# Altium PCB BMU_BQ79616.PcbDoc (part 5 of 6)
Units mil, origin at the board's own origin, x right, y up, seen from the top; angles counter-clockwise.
Board outline 7605 x 4005 mil, 4 copper layers (Top Layer, Layer 1, Layer 2, Bottom Layer), stack 37.446 mil thick; 709 components, 447 nets, 2028 pads, 1862 vias.
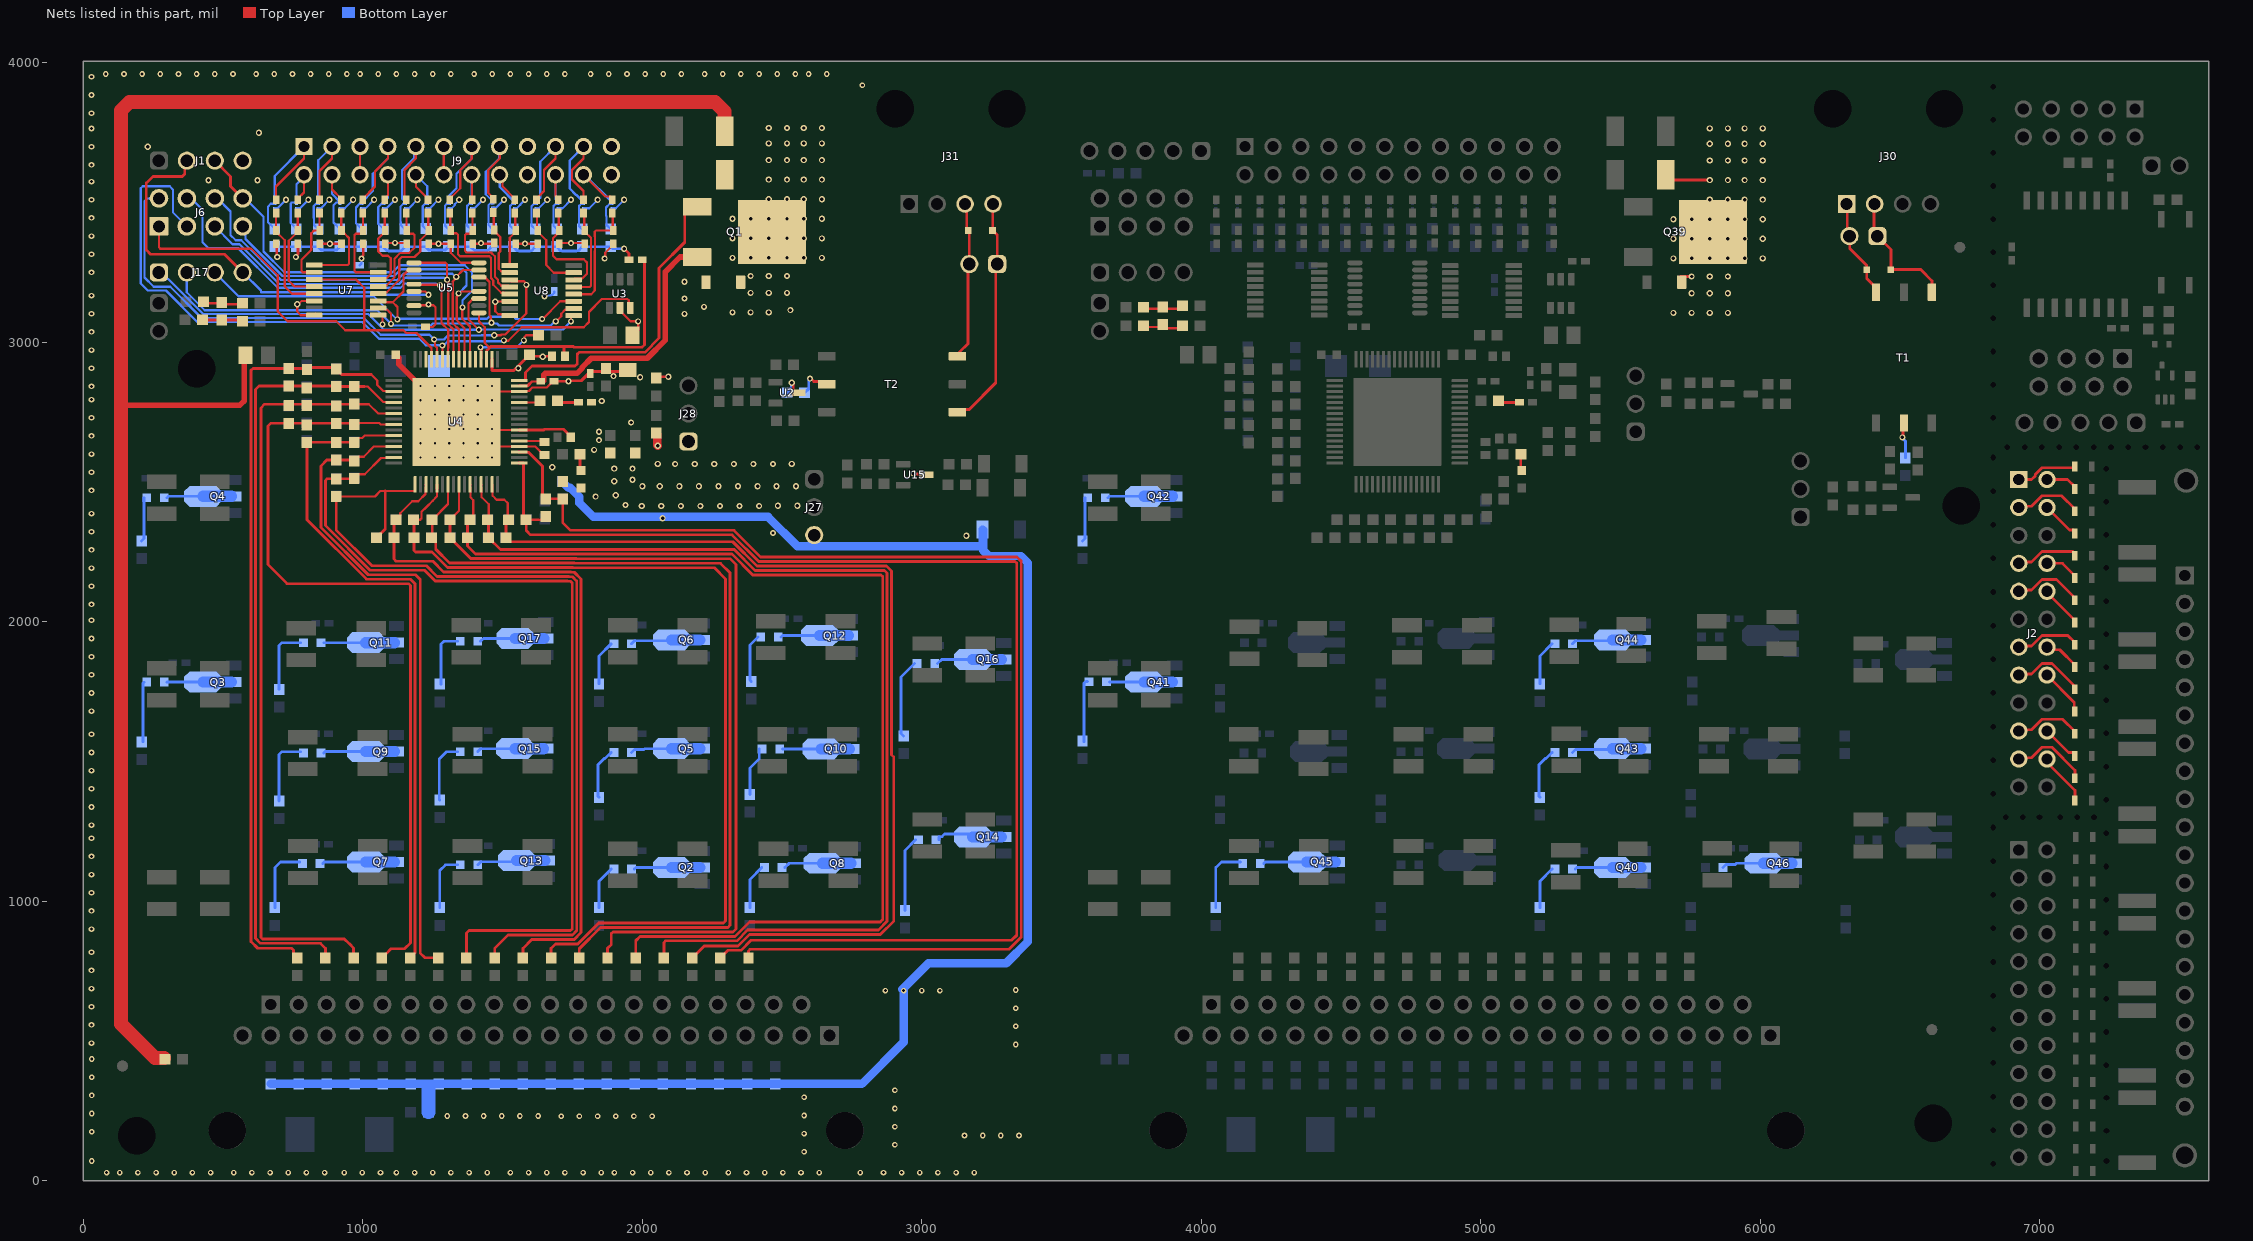
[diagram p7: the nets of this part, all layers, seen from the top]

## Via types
v1: diameter 20, hole 10, Top Layer to Bottom Layer, tented both sides, 1385 vias
v2: diameter 22.01, hole 12.01, Top Layer to Bottom Layer, tented both sides, 405 vias
v3: diameter 19.68, hole 7.87, Top Layer to Bottom Layer, 72 vias

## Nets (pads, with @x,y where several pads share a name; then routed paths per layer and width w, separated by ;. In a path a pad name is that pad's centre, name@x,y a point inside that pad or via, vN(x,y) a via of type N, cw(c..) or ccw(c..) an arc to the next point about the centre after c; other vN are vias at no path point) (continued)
A2_GND: C3.1 C8.2 C9.2 C10.1 C11.1 C12.1 C14.2 C16.1 C17.2 C18.1 C19.1 C20.2 C21.2 C22.2 C23.2 C24.2 C25.2 C26.2 C27.2 C28.2 C29.2 C31.2 C32.2 C33.2 C34.2 C35.2 C36.2 C37.2 C38.2 C39.1 C42.2 C43.2 C47.2 C50.2 C51.2 C79.2 C82.2 C83.2 C84.2 C85.2 C86.2 C88.2 C89.2 C90.2 C91.2 C92.2 C93.2 C94.2 C95.2 C96.2 C97.2 C98.2 C99.2 C100.2 C101.2 C102.2 C152.2 C153.1 D1.1 D2.2 D6.2 D7.2 D36.2 D37.2 D38.2 D39.2 D40.2 D43.2 D46.2 D49.2 D50.2 D51.2 D52.2 D53.2 D54.2 D55.2 J1.4 J9.5 J9.6 J9.11 J9.12 J9.17 J9.18 J9.23 J9.24 J27.3 J28.1 R9.1 U2.3 U3.2 U4.36 U4.39 U4.46 U4.50 U4.65 U5.8 U5.15 U7.6 U7.8 U8.6 U8.8 U15.3 | length 11070.7
  Top Layer w8: U7.6@826,3148.23 781.01,3148.23 768.79,3136 v2(765,3136) 765,3110 777.95,3097.05 U7.8@826,3097.05 U7.8@830.86,3101.91 ; C27.2@845.41,3352.76 C29.2@923.41,3352.76 ; J9.6@989.41,3599.61 J9.5@989.41,3700.39 ; v2(995,3300) 995,3303.79 1001.41,3310.2 C32.2@1001.41,3352.76 ; C34.2@1079.41,3352.76 1082.34,3355.69 1154.48,3355.69 C36.2@1157.41,3352.76 ; U5.15@1182.86,3131.02 1184.72,3132.88 1232.88,3132.88 v2(1235,3135) 1235.71,3135 1239.54,3131.17 1239.54,3133.07 1241.47,3135 1241.47,3132.32 1252.68,3132.32 1260,3125 1260,3065 1250,3055 C12.1@1223.62,3055 ; C38.2@1235.41,3352.76 v2(1270.42,3352.76) C22.2@1314.41,3352.76 1314.41,3320.79 1350.63,3284.57 U5.8@1415.14,3284.57 ; J9.12@1289.41,3599.61 J9.11@1289.41,3700.39 ; C24.2@1393.41,3352.76 1467.76,3352.76 C26.2@1470,3355 ; v3(1462.36,2638.82) 1474.17,2627.01 U4.36@1558.82,2627.01 1616.42,2627.01 1647.05,2596.38 C16.1@1650,2596.38 ; v3(1462.36,2690) 1466.3,2686.06 U4.39@1558.82,2686.06 ; v3(1462.36,2792.36) 1462.36,2798.33 1487.89,2823.86 U4.46@1558.82,2823.86 1560.72,2825.76 1594.11,2825.76 1606.54,2838.19 1657.87,2838.19 1679.68,2860 C11.1@1683.62,2860 ; U8.6@1525.83,3145 1525.02,3145.81 1474.51,3145.81 v2(1473.7,3145) 1473.7,3111.3 1484.71,3100.29 1520.97,3100.29 U8.8@1525.83,3095.43 U8.8@1530.69,3100.29 ; C28.2@1547.41,3352.76 C31.2@1625.41,3352.76 ; C33.2@1703.41,3352.76 1705.65,3355 1792.17,3355 C35.2@1794.41,3352.76 ; v2(1865,3300) 1867.68,3302.68 1867.68,3320.09 1896.41,3348.82 C37.2@1896.41,3352.76 ; U3.2@1920,3113.52 1934.59,3098.93 ; 1934.59,3098.33 1957.92,3075 v2(1985,3075) 1985,3045 C8.2@1965,3025 C8.2@1965,3031.5
  Top Layer w10: C23.2@689.41,3352.76 691.5,3350.67 691.5,3307.4 v2(693.58,3305.32) ; v2(760,3305) 760,3308.25 767.41,3315.66 C25.2@767.41,3352.76 ; C14.2@1118,2955 C14.2@1128,2945 ; v3(1206.46,2843.54) v3(1257.64,2792.36) U4.65@1334.41,2715.59 v3(1308.82,2741.18) ; 1463.27,2908.93 1463.27,2939.09 U4.50@1462.36,2940 1462.36,2900 1462.89,2899.47 1539.98,2899.47 1595.51,2955 1600.51,2950 C9.2@1676.38,2950 ; U4.39@1558.82,2686.06 1647.63,2686.06 1650.29,2688.72 1717.86,2688.72 1743.62,2662.95 C19.1@1743.62,2660 ; C11.1@1683.62,2860 1683.87,2860.25 1735.38,2860.25 1735.63,2860 1738,2862.38 1781.32,2862.38 1810,2891.06 1810,2895 1925,2895 C17.2@1935,2905 ; U3.2@1920,3113.52 U3.2@1920,3123.37 ; C51.2@2046.5,2875 C51.2@2050,2871.5 2055.14,2876.63 v2(2093.16,2876.63) ; v2(2535,2855) 2535,2851.75 2539.94,2846.81 2539.94,2826.81 2546.75,2820 U2.3@2559.25,2820 ; J27.3@2610,2305 J27.3@2615,2310 ; v2(2970,2530) 2971.85,2528.15 3014.17,2528.15 U15.3@3016.02,2526.3
  Top Layer w20: C14.2@1128,2945 1128,2922 v3(1206.46,2843.54)
  Top Layer w30: C50.2@2050,2675 2053.7,2671.3 2053.7,2631.3 v2(2055,2630)
  Bottom Layer w8: D7.2@684.41,3475.32 684.41,3477.78 686.31,3479.68 694.68,3479.68 v2(725,3510) ; D37.2@762.41,3475.39 762.41,3477.85 764.31,3479.75 774.75,3479.75 v2(805,3510) ; D39.2@840.41,3475.39 840.41,3477.85 842.31,3479.76 849.76,3479.76 v2(880,3510) ; D43.2@918.41,3475.39 918.41,3477.85 920.31,3479.76 934.76,3479.76 v2(965,3510) ; C20.2@987.76,3275 995,3282.24 v2(995,3300) ; D49.2@996.41,3475.39 996.41,3477.85 998.31,3479.76 1009.76,3479.76 v2(1040,3510) ; D51.2@1074.41,3475.4 1074.41,3477.86 1076.32,3479.76 1084.76,3479.76 v2(1115,3510) ; D53.2@1152.41,3475.39 1152.41,3477.85 1154.31,3479.76 1164.76,3479.76 v2(1195,3510) ; D55.2@1230.41,3475.4 1230.41,3477.86 1232.31,3479.77 1239.77,3479.77 v2(1270,3510) ; D6.2@1309.41,3475.38 1309.41,3477.84 1311.31,3479.75 1317.58,3479.75 1328.73,3490.9 1328.73,3493.73 v2(1345,3510) ; D36.2@1388.41,3475.39 1388.41,3477.85 1390.31,3479.75 1399.75,3479.75 v2(1430,3510) ; D38.2@1465,3477.64 1465,3480.1 1466.91,3482 1477,3482 v2(1505,3510) ; D40.2@1542.41,3475.39 1542.41,3477.85 1544.31,3479.76 1550.58,3479.76 1563,3492.18 1563,3493 v2(1580,3510) ; D46.2@1620.41,3475.39 1620.41,3477.85 1622.31,3479.76 1629.76,3479.76 v2(1660,3510) ; v2(1650,3165) 1652.68,3167.68 1671.3,3167.68 1673.25,3169.63 1677.19,3169.63 1685,3177.44 C21.2@1685,3181.38 ; D50.2@1698.41,3475.4 1698.41,3477.86 1700.31,3479.77 1714.77,3479.77 v2(1745,3510) ; D52.2@1789.41,3475.39 1789.41,3477.85 1791.31,3479.76 1809.76,3479.76 v2(1840,3510) ; D54.2@1891.41,3475.4 1891.41,3477.86 1893.31,3479.76 1904.76,3479.76 v2(1935,3510)
  Bottom Layer w10: C47.2@2517.91,2820 2518.9,2820 2532.6,2833.7 2532.6,2849.35 2535,2851.75 v2(2535,2855)
  Bottom Layer w20: 1210,340.87 1215,345.87
  Bottom Layer w30: C102.2@670,345.87 C101.2@770.28,345.87 C100.2@870.56,345.87 C99.2@970.83,345.87 C98.2@1071.11,345.87 C97.2@1171.39,345.87 1215,345.87 C96.2@1271.67,345.87 C95.2@1371.94,345.87 C94.2@1472.22,345.87 C93.2@1572.5,345.87 C92.2@1672.78,345.87 C91.2@1773.05,345.87 C90.2@1873.33,345.87 C89.2@1973.61,345.87 C88.2@2073.89,345.87 C86.2@2174.17,345.87 C85.2@2274.44,345.87 C83.2@2374.72,345.87 C82.2@2475,345.87 2785.87,345.87 2935,495 v1(2935,680) ; C79.2@1715,2500.51 1736.32,2479.19 1742.4,2479.19 1774.85,2446.74 1774.85,2424.85 1824.7,2375 2450,2375 2555,2270 3217.5,2270 3217.5,2329.43 C153.1@3218.07,2330 3220,2328.07 3220,2255 3240,2235 3355,2235 3380,2210 3380,855.3 3302.46,777.77 3023.54,777.77 v1@2930.39,684.61
  Bottom Layer w50: R9.1@1234.13,245 1234.13,329.13 1235,330
  other v1: 82.95,28.75 130,28.75 195,28.75 260,28.75 325,28.75 390,28.75 455,28.75 537.95,28.75 602.95,28.75 667.95,28.75 732.95,28.75 797.95,28.75 862.95,28.75 932.95,28.75 997.95,28.75 1062.95,28.75 1120,28.75 1185,28.75 1250,28.75 1315,28.75 1380,28.75 1445,28.75 1527.95,28.75 1592.95,28.75 1657.95,28.75 1722.95,28.75 1787.95,28.75 1852.95,28.75 1900,28.75 1965,28.75 2030,28.75 2095,28.75 2160,28.75 2225,28.75 2307.95,28.75 2372.95,28.75 2437.95,28.75 2502.95,28.75 2567.95,28.75 2632.95,28.75 2780,28.75 2862.95,28.75 2927.95,28.75 2992.95,28.75 3057.95,28.75 3122.95,28.75 3187.95,28.75 30,70 2578.75,103 2903.75,128 3153,161.25 3218,161.25 3283,161.25 3348,161.25 2578.75,168 30,175 2903.75,193 1710,230 1775,230 1840,230 1905,230 1970,230 2035,230 1302.05,231.25 1367.05,231.25 1432.05,231.25 1497.05,231.25 1562.05,231.25 1627.05,231.25 2578.75,233 30,240 2903.75,258 2578.75,298 30,305 2903.75,323 30,370 30,435 3336.25,487 28.75,492.05 3336.25,552 28.75,557.05 3336.25,617 28.75,622.05 2870,680 3000,680 3065,680 3336.25,682 28.75,687.05 28.75,752.05 28.75,817.05 28.75,900 28.75,965 28.75,1030 28.75,1095 28.75,1160 28.75,1225 28.75,1272.05 28.75,1337.05 28.75,1402.05 28.75,1467.05 28.75,1532.05 28.75,1597.05 28.75,1680 28.75,1745 28.75,1810 28.75,1875 28.75,1940 28.75,2005 28.75,2062.05 28.75,2127.05 28.75,2192.05 28.75,2257.05 28.75,2322.05 28.75,2387.05 28.75,2470 28.75,2535 28.75,2600 28.75,2665 28.75,2730 28.75,2795 28.75,2842.05 28.75,2907.05 28.75,2972.05 28.75,3037.05 28.75,3102.05 28.75,3167.05 28.75,3250 28.75,3315 28.75,3380 28.75,3445 28.75,3510 28.75,3575 28.75,3635 28.75,3700 28.75,3765 28.75,3820 28.75,3885 2787.64,3920 28.75,3950 80,3960 145,3960 210,3960 275,3960 340,3960 405,3960 470,3960 535,3960 617.95,3960 682.95,3960 747.95,3960 812.95,3960 877.95,3960 942.95,3960 990,3960 1055,3960 1120,3960 1185,3960 1250,3960 1315,3960 1397.95,3960 1462.95,3960 1527.95,3960 1592.95,3960 1657.95,3960 1722.95,3960 1815,3960 1880,3960 1945,3960 2010,3960 2075,3960 2140,3960 2222.95,3960 2287.95,3960 2352.95,3960 2417.95,3960 2482.95,3960 2547.95,3960 2595,3960 2660,3960
  other v2: 3159.74,2307.83 2467.72,2317.76 2072.59,2370.04 1997.92,2414.4 2067.92,2414.4 2137.92,2414.4 2207.92,2414.4 2277.92,2414.4 2347.92,2414.4 2417.92,2414.4 2485,2415 2555,2415 1939.73,2417.83 1832.72,2447.76 1904.73,2452.83 2000,2485 2062.52,2484.68 2132.52,2484.68 2202.52,2484.68 2272.52,2484.68 2342.52,2484.68 2412.52,2484.68 2480,2485 2550,2485 1899.73,2502.83 1964.73,2507.83 1899.73,2547.83 1964.73,2547.83 1677.72,2552.76 2055,2565 2117.52,2564.68 2187.52,2564.68 2257.52,2564.68 2327.52,2564.68 2397.52,2564.68 2467.52,2564.68 2535,2565 1827.64,2615 1845,2650 1845,2680 1959.73,2712.83 1855,2790 1735.63,2860.5 1992,2875 1896.81,2878.78 1556.3,2907.13 1643.63,2948.3 2150.68,3101.69 2220.68,3126.69 2150.68,3156.69 2150.68,3216.69 881.72,3352.76 1580.28,3353.25 1422.91,3354.76 1745,3355 1114.73,3355.69 447.64,3580 622.64,3580 229.84,3700 627.64,3750
  other v3: 1206.46,2587.64 1257.64,2587.64 1308.82,2587.64 1360,2587.64 1411.18,2587.64 1462.36,2587.64 1206.46,2638.82 1257.64,2638.82 1308.82,2638.82 1360,2638.82 1411.18,2638.82 1206.46,2690 1257.64,2690 1308.82,2690 1360,2690 1411.18,2690 1206.46,2741.18 1257.64,2741.18 1360,2741.18 1411.18,2741.18 1462.36,2741.18 1206.46,2792.36 1308.82,2792.36 1360,2792.36 1411.18,2792.36 1257.64,2843.54 1308.82,2843.54 1360,2843.54 1411.18,2843.54 1462.36,2843.54
A2_GPIO1: J6.1 U4.61 U7.3 | length 1659.2
  Top Layer w8: J6.1@270,3415 270,3340 275,3335 600,3335 695,3240 695,3110 730,3075 904.6,3075 936.6,3043 1005,3043 ; U7.3@826,3225 975,3225 1005,3195 1005,3043 ; U4.61@1245.83,2940 1245.83,2979.47 1192.11,3033.19 1154.85,3033.19 1145.04,3043 1005,3043
A2_GPIO2: J6.2 U4.60 U8.3 | length 2070.7
  Top Layer w8: v2(1255,3010) 1257.68,3007.32 1257.68,2987.62 1265.26,2980.04 1265.26,2940.26 U4.60@1265.51,2940 ; v2(1470,3025) 1493,3025 1495.71,3027.71 1509.49,3027.71 1585,3103.22 1585,3210 1576.47,3218.53 1530.69,3218.53 U8.3@1525.83,3223.39
  Bottom Layer w8: J6.2@270,3515 230,3515 218.59,3503.59 218.59,3231.82 251.41,3199 310.8,3199 422.8,3087 1003.3,3087 1063.55,3026.75 1238.25,3026.75 v2(1255,3010) 1289.98,3010 1303.97,3024 1423.7,3024 1424.7,3025 v2(1470,3025)
  other v2: 1585,3205.55
A2_GPIO3: J6.3 U3.3 U4.59 | length 2641.4
  Top Layer w8: v2(1284.55,2988.56) 1284.87,2988.24 1284.87,2940.32 U4.59@1285.2,2940 ; v2(1504.52,3006.7) 1505.96,3005.26 1520.26,3005.26 1568.8,3053.8 1790,3053.8 1808.8,3072.6 1808.8,3108.8 1855.02,3155.02 1946.42,3155.02 1951.11,3150.33 1951.11,3115.11 U3.3@1957.4,3108.82
  Bottom Layer w8: J6.3@370,3415 320,3465 320,3546.93 308.46,3558.46 212,3558.46 204.59,3551.06 204.59,3210 229.59,3185 295,3185 407,3073 997.5,3073 1057.75,3012.75 1201.25,3012.75 1225,2989 1284.11,2989 v2(1284.55,2988.56) 1288.34,2988.56 1303.77,3004 1477.51,3004 ; 1477.54,3004.02 1501.84,3004.02 v2(1504.52,3006.7)
A2_GPIO4: J6.4 U4.58 U5.12 | length 1490
  Top Layer w8: U5.12@1182.86,3207.8 1184.72,3205.94 1273.77,3205.94 v2(1275.71,3204) ; v2@1275.71,3207.8 1275.71,3200.21 1280.91,3195 1280.91,3069.29 1305.55,3044.65 1305.55,2979.86 1304.88,2979.19 U4.58@1304.88,2940
  Bottom Layer w8: J6.4@370,3515 385,3515 425.64,3474.36 425.64,3357.89 446.29,3337.25 552.75,3337.25 695,3195 1135,3195 1150,3210 1259.8,3210 1263.12,3206.68 1273.03,3206.68 v2(1275.71,3204)
A2_GPIO5: J6.5 U4.57 U5.9 | length 1396.5
  Top Layer w8: U5.9@1182.86,3284.57 1295.43,3284.57 1301.45,3278.55 v2(1301.45,3223.89) ; v2@1305.23,3223.89 1305.23,3064.77 1324.57,3045.43 U4.57@1324.57,2940
  Bottom Layer w8: J6.5@470,3415 533.75,3351.25 558.55,3351.25 700.8,3209 1129,3209 1151,3231 1290.55,3231 1297.66,3223.89 v2(1301.45,3223.89)
A2_GPIO6: J6.6 U4.56 U5.7 | length 1449
  Top Layer w8: U4.56@1344.25,2940 1344,2940.26 1344,3046 1321.57,3068.43 1321.57,3217.89 1333.89,3230.21 1333.89,3235 1357.87,3258.98 U5.7@1415.14,3258.98
  Bottom Layer w8: J6.6@470,3515 480,3515 526.54,3468.46 526.54,3383.46 544.75,3365.25 564.35,3365.25 706.6,3223 1123.2,3223 1145.2,3245 1320.1,3245 1331.11,3234 v2(1333.89,3234)
A2_GPIO7: J6.7 U4.55 U5.4 | length 1303.1
  Top Layer w8: U4.55@1363.94,2940 1363.94,3050.66 1341.71,3072.89 1341.71,3073.29 1335.57,3079.43 1335.57,3164.21 1342.58,3171.21 v2(1342.58,3175) 1346.37,3175 1353.57,3182.2 U5.4@1396.14,3182.2
  Bottom Layer w8: J6.7@570,3415 579.86,3405.14 579.86,3369.54 712.4,3237 1112,3237 1136,3261 1246.79,3261 1247.5,3261.71 1358.29,3261.71 1371,3249 1371,3203.43 v2(1342.58,3175)
A2_GPIO8: J1.3 J6.8 U4.54 | length 1525
  Top Layer w8: v2@1355.71,3115 1355.71,3084.5 1383.62,3056.58 U4.54@1383.62,2940
  Top Layer w10: J1.3@470,3650 526.52,3593.48 526.52,3558.48 J6.8@570,3515
  Bottom Layer w8: J6.8@570,3515 578.42,3515 644.6,3448.83 644.6,3324.6 718.2,3251 1106.2,3251 1130.91,3275.71 1364.61,3275.71 1390,3250.31 1390,3183.61 1356.58,3150.18 v2(1356.58,3125)
A2_LDOIN: C11.2 Q1.3 U4.47 | length 1010.1
  Top Layer w8: U4.47@1558.82,2843.54 1559.72,2844.45 1560.72,2845.45 1590.45,2845.45 1593.23,2848.23 1593.67,2848.23 ; 1603.72,2858.29 1605.44,2860 C11.2@1636.38,2860
  Top Layer w10: U4.47@1559.72,2844.45 1589.89,2844.45 1593.67,2848.23 1603.72,2858.29
  Top Layer w20: C11.2@1647.13,2861.81 1647.13,2883.14 1652.98,2889 1766.03,2889 1785.19,2908.16 1785.19,2911 1817.19,2943 2017.7,2943 2082.5,3007.8 2082.5,3252.5 2135.24,3305.24 Q1.3@2196.14,3305.24
A2_NEG5V: R68.1 U4.44 | length 76
  Top Layer w8: U4.44@1558.82,2784.49 1627.01,2784.49 R68.1@1632.52,2790
A2_NFAULT: U4.62
A2_NPNB: Q1.1 U4.48 | length 1136.8
  Top Layer w10: U4.48@1558.82,2863.23 1580.49,2863.23 1581.4,2864.13 1581.4,2891.4 1605,2915 1759.49,2915 1767,2922.51 1767,2957 1774,2964 2009,2964 2060,3015 2060,3266.22 2151.85,3358.07 2151.85,3458.27 2178.35,3484.76 Q1.1@2196.14,3484.76
A2_NTC0: C23.1 R34.2 U7.5 | length 416.3
  Top Layer w8: R34.2@689.41,3462.76 C23.1@689.41,3400 689.41,3396.06 720,3365.47 720,3200 746.18,3173.82 U7.5@850,3173.82
A2_NTC0_C: D7.1 J9.1 R33.2 R34.1 | length 597.6
  Top Layer w8: R34.1@689.41,3510 689.41,3557.46 789.41,3657.46 J9.1@789.41,3700.39
  Bottom Layer w8: R33.2@684.41,3405 684.41,3405.98 660.39,3430 660.39,3485.39 670.55,3495.55 682.5,3495.55 684.41,3497.46 D7.1@684.41,3499.92 684.41,3595.39 J9.1@789.41,3700.39
A2_NTC1: C25.1 R38.2 U7.4 | length 379.7
  Top Layer w8: R38.2@767.08,3462.76 767.24,3462.59 767.24,3395.9 735,3363.65 735,3220 755.59,3199.41 U7.4@850,3199.41
A2_NTC1_C: D37.1 J9.2 R37.2 R38.1 | length 332.2
  Top Layer w8: R38.1@767.08,3510 767.08,3513.94 789.41,3536.27 J9.2@789.41,3599.61
  Bottom Layer w8: R37.2@762.08,3405 762.08,3405.98 741.53,3426.53 741.53,3496.83 744.7,3499.99 D37.1@762.41,3499.99 762.41,3565.93 789.41,3592.93 J9.2@789.41,3599.61
A2_NTC2: C27.1 R42.2 U7.2 | length 301.5
  Top Layer w8: U7.2@826,3250.59 784.69,3250.59 780,3255.28 780,3295 815,3330 815,3390 825,3400 C27.1@845.08,3400 ; R42.2@844.74,3462.76 845.08,3462.42 C27.1@845.08,3400 ; U7.2@845.14,3255.45 U7.2@850,3250.59 ; C27.1@845.41,3400 C27.1@845.08,3400
A2_NTC2_C: D39.1 J9.3 R41.2 R42.1 | length 544.7
  Top Layer w8: R42.1@844.74,3510 844.74,3612.79 889.41,3657.46 J9.3@889.41,3700.39
  Bottom Layer w8: R41.2@839.75,3405 825.05,3419.7 825.05,3444.95 824.5,3445.5 824.5,3487.9 832.24,3495.63 838.5,3495.63 840.41,3497.54 D39.1@840.41,3500 840.41,3651.39 883.43,3694.41 889.41,3694.41 J9.3@889.41,3700.39
A2_NTC3: C29.1 R48.2 U7.1 | length 297.4
  Top Layer w8: U7.1@850,3276.18 945.31,3276.18 950,3280.87 950,3373.41 935.16,3388.25 931.22,3388.25 923.41,3396.06 C29.1@923.41,3400 ; R48.2@922.41,3462.76 922.91,3462.26 C29.1@922.91,3400
A2_NTC3_C: D43.1 J9.4 R45.2 R48.1 | length 336.7
  Top Layer w8: J9.4@889.41,3599.61 889.41,3546.94 922.41,3513.94 R48.1@922.41,3510
  Bottom Layer w8: J9.4@889.41,3599.61 889.41,3531.46 918.41,3502.46 D43.1@918.41,3500 905,3500 895,3490 895,3428.41 917.42,3405.98 R45.2@917.42,3405
A2_NTC4: C32.1 R54.2 U7.15 | length 342.6
  Top Layer w8: R54.2@1000.08,3462.76 1000.74,3462.09 C32.1@1000.74,3396.73 ; C32.1@1001.41,3400 1001.41,3396.06 993.6,3388.25 974.69,3388.25 970,3383.57 970,3255.28 974.69,3250.59 1055.73,3250.59 1060.59,3255.45 U7.15@1047.69,3255.45
A2_NTC4_C: D49.1 J9.7 R53.2 R54.1 | length 582.2
  Top Layer w8: R54.1@1000.08,3510 1000.08,3513.94 1043.5,3557.36 1043.5,3611.55 1089.41,3657.46 J9.7@1089.41,3700.39
  Bottom Layer w8: R53.2@995.09,3405 995.09,3405.98 975,3426.08 975,3482.4 988.24,3495.63 994.5,3495.63 996.41,3497.54 D49.1@996.41,3500 996.41,3502.46 1035,3541.05 1035,3603.05 1089.41,3657.46 J9.7@1089.41,3700.39
A2_NTC5: C34.1 R58.2 U7.14 | length 290.8
  Top Layer w8: R58.2@1077.74,3462.76 1078.58,3461.92 1078.58,3397.24 C34.1@1079.41,3396.41 ; U7.14@1078.35,3228.33 1079.87,3229.86 1085,3229.86 1099.3,3244.16 1099.3,3300.7 1090,3310 1070,3310 1060,3320 1059.69,3320 1055,3324.69 1055,3371.65 1079.41,3396.06 C34.1@1079.41,3396.41 ; C34.1@1079.41,3400 C34.1@1079.41,3396.41
A2_NTC5_C: D51.1 J9.8 R57.2 R58.1 | length 314.3
  Top Layer w8: R58.1@1077.74,3510 1077.74,3513.94 1089.41,3525.6 J9.8@1089.41,3599.61
  Bottom Layer w8: R57.2@1072.77,3405 1072.77,3405.98 1055,3423.75 1055,3484.4 1066.24,3495.64 1072.51,3495.64 1074.41,3497.54 D51.1@1074.41,3500 1074.41,3502.46 1089.41,3517.46 J9.8@1089.41,3599.61
A2_NTC6: C36.1 R62.2 U7.13 | length 347.2
  Top Layer w8: U7.13@1078.35,3202.74 1079.87,3204.27 1085,3204.27 1113.3,3232.57 1113.3,3299.18 1134.12,3320 1166.35,3320 1185,3338.65 1185,3383.57 1180.31,3388.25 1165.22,3388.25 1157.41,3396.06 C36.1@1157.41,3400 1156.41,3401 1156.41,3461.76 R62.2@1155.41,3462.76
A2_NTC6_C: D53.1 J9.9 R61.2 R62.1 | length 548.5
  Top Layer w8: R62.1@1155.41,3510 1148.5,3516.91 1148.5,3616.55 1189.41,3657.46 J9.9@1189.41,3700.39
  Bottom Layer w8: R61.2@1150.44,3405 1135.74,3419.7 1135.74,3429.26 1135,3430 1135,3486.4 1144.24,3495.63 1150.5,3495.63 1152.41,3497.54 D53.1@1152.41,3500 1152.41,3502.46 1140,3514.87 1140,3615 1182.49,3657.49 1182.49,3693.47 J9.9@1189.41,3700.39
A2_NTC7: C38.1 R66.2 U7.12 | length 380
  Top Layer w8: U7.12@1078.35,3177.15 1079.87,3178.68 1085,3178.68 1130,3223.68 1130,3296.08 1138.92,3305 1185,3305 1205,3325 1205,3365.65 1235.41,3396.06 C38.1@1235.41,3400 ; R66.2@1233.08,3462.76 1234.24,3461.59 C38.1@1234.24,3401.17
A2_NTC7_C: D55.1 J9.10 R65.2 R66.1 | length 332.1
  Top Layer w8: J9.10@1189.41,3599.61 1190.31,3598.7 1190.31,3556.7 1233.08,3513.94 R66.1@1233.08,3510
  Bottom Layer w8: J9.10@1189.41,3599.61 1230.41,3558.61 D55.1@1230.41,3500.01 1230.41,3497.55 1228.5,3495.64 1222.24,3495.64 1214.5,3487.91 1214.5,3416.4 R65.2@1224.41,3406.5
A2_NTC8: C22.1 R32.2 U8.5 | length 458.9
  Top Layer w8: R32.2@1311.08,3462.76 1312.74,3461.09 1312.74,3401.67 C22.1@1314.41,3400 1319.41,3395 1319.41,3392.81 1322.22,3390 1335.31,3390 1340,3385.31 1340,3315 1347.41,3307.59 1452.61,3307.59 1458.3,3301.9 1458.3,3229.81 1466.7,3221.41 1466.7,3205.53 1495.17,3177.06 1505.14,3177.06 1510,3172.2 U8.5@1520.83,3172.2
A2_NTC8_C: D6.1 J9.13 R31.2 R32.1 | length 567.4
  Top Layer w8: R32.1@1311.08,3510 1311.08,3513.94 1348.5,3551.37 1348.5,3616.55 1389.41,3657.46 J9.13@1389.41,3700.39
  Bottom Layer w8: R31.2@1306.12,3405 1293.5,3417.62 1293.5,3488.82 1300.31,3495.62 1307.5,3495.62 1309.41,3497.52 D6.1@1309.41,3499.99 1309.41,3525.59 1335,3551.18 1335,3603.05 1389.41,3657.46 J9.13@1389.41,3700.39
A2_NTC9: C24.1 R36.2 U8.4 | length 425.2
  Top Layer w8: C24.1@1385.6,3395 C24.1@1385.6,3390 ; R36.2@1390.74,3462.76 1392.08,3461.42 1392.08,3401.33 C24.1@1393.41,3400 1393.41,3397.81 C24.1@1385.6,3390 ; U8.4@1525.83,3197.8 1520.97,3202.65 1495.17,3202.65 1483.74,3214.09 1483.74,3224.17 1472.3,3235.61 1472.3,3307.7 1458.41,3321.59 1370.86,3321.59 1365,3327.45 1365,3383.57 1369.69,3388.25 1385.6,3388.25 C24.1@1385.6,3390
A2_NTC9_C: D36.1 J9.14 R35.2 R36.1 | length 300.9
  Top Layer w8: J9.14@1389.41,3599.61 1390.08,3598.94 1390.08,3510.67 R36.1@1390.74,3510
  Bottom Layer w8: R35.2@1385.78,3405 1372.5,3418.27 1372.5,3487.9 1380.24,3495.63 1386.5,3495.63 1388.41,3497.53 D36.1@1388.41,3499.99 1388.91,3500.49 1388.91,3599.11 J9.14@1389.41,3599.61
A2_NTC10: C26.1 R40.2 U8.2 | length 255.1
  Top Layer w8: R40.2@1467,3465 1467,3461.06 1468.5,3459.56 1468.5,3403.74 C26.1@1470,3402.24 1470,3398.31 1491.81,3376.5 1491.81,3324.86 1486.3,3319.35 1486.3,3262.71 1495.17,3253.83 1515.97,3253.83 U8.2@1520.83,3248.98
A2_NTC10_C: D38.1 J9.15 R39.2 R40.1 | length 552.3
  Top Layer w8: R40.1@1467,3512.24 1467,3516.18 1448.5,3534.68 1448.5,3616.55 1489.41,3657.46 J9.15@1489.41,3700.39
  Bottom Layer w8: R39.2@1462.04,3407.24 1449.09,3420.19 1449.09,3490.15 1456.83,3497.88 1463.09,3497.88 1465,3499.78 D38.1@1465,3502.24 1465,3504.7 1440,3529.7 1440,3610 1487.49,3657.49 1487.49,3698.47 J9.15@1489.41,3700.39
A2_NTC11: C28.1 R44.2 U8.1 | length 201
  Top Layer w8: U8.1@1520.83,3274.57 1525.6,3279.34 1525.6,3374.25 1547.41,3396.06 C28.1@1547.41,3400 1545.58,3401.83 1545.58,3460.92 R44.2@1543.74,3462.76 ; U8.1@1525.83,3274.57 U8.1@1526.04,3274.78
A2_NTC11_C: D40.1 J9.16 R43.2 R44.1 | length 344
  Top Layer w8: J9.16@1489.41,3599.61 1499.71,3589.31 1499.71,3557.97 1543.74,3513.94 R44.1@1543.74,3510
  Bottom Layer w8: J9.16@1489.41,3599.61 1489.41,3555.46 1542.41,3502.46 D40.1@1542.41,3500 1542.41,3497.54 1540.5,3495.63 1534.24,3495.63 1526.5,3487.9 1526.5,3417.29 R43.2@1538.79,3405
A2_NTC12: C31.1 R52.2 U8.15 | length 310.2
  Top Layer w8: R52.2@1621.41,3462.76 1623.41,3460.76 1623.41,3402 C31.1@1625.41,3400 1625.41,3396.06 1655.87,3365.6 1655.87,3276.48 1683.38,3248.98 U8.15@1754.17,3248.98
A2_NTC12_C: D46.1 J9.19 R49.2 R52.1 | length 558.5
  Top Layer w8: R52.1@1621.41,3510 1621.41,3513.94 1648.5,3541.03 1648.5,3616.55 1689.41,3657.46 J9.19@1689.41,3700.39
  Bottom Layer w8: R49.2@1616.46,3405 1603.62,3417.84 1603.62,3487.02 1612.24,3495.63 1618.5,3495.63 1620.41,3497.54 D46.1@1620.41,3500 1620.41,3502.46 1635,3517.05 1635,3645.98 J9.19@1689.41,3700.39
A2_NTC13: C33.1 R56.2 U8.14 | length 393.3
  Top Layer w8: R56.2@1699.08,3462.76 1701.24,3460.59 1701.24,3402.17 C33.1@1703.41,3400 1698.41,3395 1698.41,3391.06 1680,3372.65 1680,3310 1692.75,3297.25 1789.97,3297.25 1802,3285.22 1802,3245.42 1784.83,3228.24 1759.03,3228.24 U8.14@1754.17,3223.39
A2_NTC13_C: D50.1 J9.20 R55.2 R56.1 | length 307
  Top Layer w8: J9.20@1689.41,3599.61 1689.41,3523.6 1699.08,3513.94 R56.1@1699.08,3510
  Bottom Layer w8: J9.20@1689.41,3599.61 1689.41,3511.47 1698.41,3502.47 D50.1@1698.41,3500.01 1698.41,3497.55 1696.5,3495.64 1690.24,3495.64 1682.5,3487.91 1682.5,3416.63 R55.2@1694.13,3405
A2_NTC14: C35.1 R60.2 U8.13 | length 334.2
  Top Layer w8: U8.13@1754.17,3197.8 1811.31,3197.8 1816,3202.48 1816,3332.65 1816.22,3332.87 1816.22,3374.25 1794.41,3396.06 C35.1@1794.41,3400 ; R60.2@1789.41,3462.76 1791.91,3460.26 C35.1@1791.91,3400
A2_NTC14_C: D52.1 J9.21 R59.2 R60.1 | length 576.5
  Top Layer w8: R60.1@1789.41,3510 1789.41,3541.76 1748.5,3582.66 1748.5,3616.55 1789.41,3657.46 J9.21@1789.41,3700.39
  Bottom Layer w8: R59.2@1784.48,3405 1773.5,3415.97 1773.5,3487.9 1781.24,3495.63 1787.5,3495.63 1789.41,3497.54 D52.1@1789.41,3500 1789.41,3502.46 1764.69,3527.18 1762.82,3527.18 1740,3550 1740,3650.98 J9.21@1789.41,3700.39
A2_NTC15: C37.1 R64.2 U8.12 | length 424.7
  Top Layer w8: U8.12@1754.17,3172.2 1817.2,3172.2 1830,3185 1830,3326.85 1830.22,3327.07 1830.22,3378.45 1830,3378.67 1830,3395.31 1834.69,3400 C37.1@1896.41,3400 1894.08,3402.33 1894.08,3460.42 R64.2@1891.74,3462.76
A2_NTC15_C: D54.1 J9.22 R63.2 R64.1 | length 401
  Top Layer w8: J9.22@1789.41,3599.61 1867.27,3521.75 1883.93,3521.75 1891.74,3513.94 R64.1@1891.74,3510
  Bottom Layer w8: J9.22@1789.41,3599.61 1794.27,3599.61 1891.41,3502.46 1891.41,3497.54 1889.5,3495.64 1883.24,3495.64 1870,3482.4 1870,3452.59 1872.1,3450.49 1872.1,3419.7 R63.2@1886.8,3405
A2_PULLUP: R31.1 R33.1 R35.1 R37.1 R39.1 R41.1 R43.1 R45.1 R49.1 R53.1 R55.1 R57.1 R59.1 R61.1 R63.1 R65.1 R189.1 | length 1372.4
  Top Layer w10: v2(1935,3335) 1952.76,3317.24 R189.1@1952.76,3295
  Bottom Layer w10: R33.1@684.41,3342.01 R37.1@762.08,3342.01 R41.1@839.75,3342.01 851.01,3330.75 906.17,3330.75 R45.1@917.42,3342.01 R53.1@995.09,3342.01 R57.1@1072.77,3342.01 1072.77,3341.02 1086.47,3327.32 1091.51,3327.32 1092.32,3326.51 1130.88,3326.51 1131.69,3327.32 1136.74,3327.32 1150.44,3341.02 R61.1@1150.44,3342.01 1224.41,3342.01 1235.67,3330.75 1294.86,3330.75 R31.1@1306.12,3342.01 R35.1@1385.78,3342.01 1399.03,3328.76 1447.53,3328.76 1460.78,3342.01 R43.1@1538.79,3342.01 1538.79,3341.02 1552.49,3327.32 1557.54,3327.32 1558.35,3326.51 1596.9,3326.51 1597.71,3327.32 1602.76,3327.32 1616.46,3341.02 R49.1@1616.46,3342.01 R55.1@1694.13,3342.01 1694.13,3341.02 1707.83,3327.32 1712.88,3327.32 1713.69,3326.51 1764.92,3326.51 1765.73,3327.32 1770.77,3327.32 1784.48,3341.02 R59.1@1784.48,3342.01 R63.1@1886.8,3342.01 1893.81,3335 v2(1935,3335)
A2_PWR: R25.2 R29.1 R192.1 | length 6352.9
  Top Layer w20: 135,2775 560,2775 575,2790 575,2920 575,2948.31 R29.1@576.69,2950
  Top Layer w30: R192.1@288.31,438.7 R192.1@292.01,435 ; R25.2@2294.42,3746.13 R25.2@2295.55,3745
  Top Layer w50: R192.1@288.31,438.7 256.3,438.7 135,560 135,2775 135,3830 165,3860 2260,3860 2294.42,3825.58 R25.2@2294.42,3746.13
A2_REFHP: C16.2 U4.37 | length 92.5
  Top Layer w8: U4.37@1558.82,2646.69 1646.93,2646.69 C16.2@1650,2643.62
A2_RHS_T_MUX: J1.2 J17.4 U5.13 | length 1578.6
  Top Layer w8: U5.13@1182.86,3182.2 1222.42,3182.2 1234.62,3170 v2(1235,3170)
  Top Layer w10: J1.2@370,3650 362.52,3642.52 362.52,3602.52 353.49,3593.49 248.49,3593.49 224.92,3569.92 224.92,3330.08 240,3315 505,3315 J17.4@570,3250
  Bottom Layer w8: J17.4@570,3250 635,3185 635,3179 1044.34,3179 1053.34,3170 v2(1235,3170)
A2_RX: R153.1 U4.52 | length 265.5
  Top Layer w8: U4.52@1422.99,2940 1424.9,2941.91 v2@1424.9,2973.9 ; v2(1576.06,3006.91) 1578.74,3009.59 1578.74,3018.94 1584.8,3025 R153.1@1628.5,3025
  Bottom Layer w8: v2(1421.06,2981.91) 1551.06,2981.91 v2(1576.06,3006.91)
A2_THER_A0: J17.3 U5.10 U7.11 U8.11 | length 1640.2
  Top Layer w8: U7.11@1078.35,3148.23 1083.2,3143.37 1106.69,3143.37 ; v2(1123.54,3082.01) 1123.54,3126.51 1106.69,3143.37 ; U5.10@1178.86,3258.98 1163.08,3258.98 1145.3,3241.2 1145.3,3181.98 1106.69,3143.37 ; v2(1641.46,3083.5) 1643.21,3083.5 1706.32,3146.61 U8.11@1754.17,3146.61
  Bottom Layer w8: J17.3@470,3250 555,3165 1038.54,3165 1121.53,3082.01 v2(1123.54,3082.01) 1125.37,3083.84 1444.13,3083.84 1451.3,3091.01 1540.73,3091.01 1548.24,3083.5 v2(1641.46,3083.5)
A2_THER_A1: J17.2 U5.6 U7.10 U8.10 | length 1801.4
  Top Layer w8: U7.10@1078.35,3119.31 1079.87,3117.78 1085,3117.78 1100.39,3102.39 v2(1100.39,3066) ; U5.6@1415.14,3233.39 1434.92,3233.39 1452.7,3215.61 1452.7,3097.01 1457.32,3092.39 1457.32,3072.68 v2(1460,3070) ; v2(1690,3074.8) 1691.1,3074.8 1709.65,3093.35 1709.65,3102.29 1723.52,3116.17 1749.31,3116.17 U8.10@1754.17,3121.02
  Bottom Layer w8: J17.2@370,3250 370,3179.4 434.4,3115 1051.4,3115 v2(1100.39,3066) ; v2@1097.59,3063.2 1100.39,3060.39 1242.91,3060.39 1249.52,3067.01 1448.31,3067.01 1448.63,3067.32 v2@1459.16,3067.32 ; v2(1460,3070) 1462.68,3067.32 1479.68,3067.32 1487,3060 1672.27,3060 1687.07,3074.8 v2(1690,3074.8)
A2_THER_A2: J17.1 U5.3 U7.9 U8.9 | length 1791.4
  Top Layer w8: v2(1070,3064) U7.9@1070,3092.19 ; v2(1415,3045) 1377.58,3082.42 1377.58,3138.84 1395.36,3156.61 U5.3@1415.14,3156.61 ; v2(1745,3075) 1745,3090.57 1749.86,3095.43 U8.9@1754.17,3095.43
  Bottom Layer w8: J17.1@270,3250 276.62,3250 300.03,3226.59 303.01,3226.59 428.6,3101 1019,3101 v2@1063,3057 ; v2(1070,3064) v2@1063,3057 ; v2(1745,3075) 1716,3046 1416,3046 v2(1415,3045) 1075,3045 v2@1063,3057
A2_TSREF: C9.1 R189.2 U4.51 U5.1 | length 1085.2
  Top Layer w8: U5.1@1415.14,3105.43 1415.14,3074.56 1436,3053.7 1436,2997.57 1453.04,2980.53 ; 1705,2984.7 1705,2985
  Top Layer w10: U4.51@1442.68,2940 1443.58,2940.91 1443.58,2971.07 1453.04,2980.53 1457.22,2984.7 1705,2984.7 1720,2984.7 1753.25,2984.7 1755.45,2982.5 1999.44,2982.5 2007.5,2990.56 2007.5,3287.5 R189.2@2000,3295 ; 1720,2980 1720,2953.62 C9.1@1723.62,2950
A2_TX: U4.53
A2_VC0: C80.2 C84.1 R225.2 U4.35 | length 4431
  Top Layer w10: U4.35@1558.82,2607.32 1559.72,2606.42 1592.83,2606.42 1642.91,2556.33 1642.91,2452.09 C80.2@1651.5,2443.5 ; C80.2@1655,2440 1713.5,2440 C84.1@1715,2438.5 1715,2355 1743,2327 2328,2327 2423.35,2231.65 3321.85,2231.65 3340.77,2231.65 3356,2216.42 3356,2197.5 3356,871.57 3312.24,827.81 2385.86,827.81 2380,821.95 R225.2@2380,796.5
A2_VC1: C76.2 C80.1 R209.2 U4.33 | length 4562.9
  Top Layer w10: U4.33@1558.82,2567.95 1573.5,2567.95 1574.41,2567.05 C76.2@1574.41,2365 ; C80.1@1655,2377.01 1642.99,2365 C76.2@1584.41,2365 1584.41,2326.59 1600,2311 2321.37,2311 2416.73,2215.65 3334.14,2215.65 3340,2209.79 3340,878.2 3321.8,860 2389.56,860 2353.56,824 2305.58,824 2279.06,797.48 R209.2@2279.06,796.5
A2_VC2: C72.2 C76.1 R193.2 U4.31 | length 3697.1
  Top Layer w8: U4.31@1462.36,2491.18 1464.27,2489.28 1464.27,2450.53 1477.98,2436.82 1505.95,2436.82 1518.18,2424.59 1518.18,2368.24 C76.1@1521.42,2365
  Top Layer w10: C76.1@1521.42,2365 1512.4,2355.98 C72.2@1512.4,2300 1526.1,2286.3 2323.45,2286.3 2410.1,2199.65 2858.63,2199.65 2873.33,2199.65 2892.08,2180.9 2892.08,1523.23 2900,1515.3 2900,929.25 2851.41,880.66 2383.55,880.66 2342.88,840 2221.63,840 2192.81,811.18 2191.83,811.18 2190,809.36 2190,808.37 R193.2@2178.12,796.5
A2_VC3: C68.2 C72.1 R176.2 U4.29 | length 3806.5
  Top Layer w8: U4.29@1422.99,2491.18 U4.29@1424.9,2489.28 ; U4.29@1424.9,2479.28 1424.9,2445.1 1450,2420 1450,2369.09 C68.2@1445.91,2365
  Top Layer w10: C68.2@1445.91,2365 1449.41,2361.5 C72.1@1449.41,2300 1450.39,2300 1492.14,2258.25 2328.86,2258.25 2403.47,2183.65 2866.7,2183.65 2876.08,2174.27 2876.08,927.96 2844.78,896.66 2376.92,896.66 2338.25,858 2083.05,858 2077.19,852.14 R176.2@2077.19,796.5
A2_VC4: C64.2 C68.1 R160.2 U4.27 | length 3959
  Top Layer w8: C68.1@1382.91,2365 1395,2377.09 1395,2435 1385.53,2444.47 U4.27@1385.53,2479.28 ; U4.27@1383.62,2491.18 U4.27@1385.53,2489.28
  Top Layer w10: C68.1@1382.91,2365 1374.41,2356.5 C64.2@1374.41,2300 1374.41,2270.59 1402.75,2242.25 2320.37,2242.25 2394.98,2167.65 2854.22,2167.65 2860.08,2161.79 2860.08,934.58 2851.29,925.8 2383.42,925.8 2331.63,874 1991.91,874 1976.25,858.34 R160.2@1976.25,796.5
A2_VC5: C60.2 C64.1 R144.2 U4.25 | length 3108.6
  Top Layer w8: C60.2@1311.89,2365 1344.25,2397.36 U4.25@1344.25,2481.18
  Top Layer w10: C60.2@1311.89,2365 1311.89,2300.47 C64.1@1311.42,2300 1312.4,2300 1386.15,2226.25 1764.35,2226.25 1765.6,2225 2315,2225 2335,2205 2335,900 2325,890 1894.87,890 1889.01,884.14 1889.01,845.2 1875.31,831.5 R144.2@1875.31,796.5
A2_VC6: C56.2 C60.1 R128.2 U4.23 | length 3210.7
  Top Layer w8: C60.1@1247.91,2365 1248.9,2365 1304.88,2420.98 U4.23@1304.88,2481.18
  Top Layer w10: C60.1@1247.91,2365 1247.91,2302.01 C56.2@1245.91,2300 1246.89,2300 1260.59,2286.3 1260.59,2259.41 1309.75,2210.25 1757.72,2210.25 1758.98,2209 2280.14,2209 2314,2175.14 2314,1552.76 2314,914 2306,906 1850.51,906 1774.38,829.87 R128.2@1774.38,796.5
A2_VC7: C52.2 C56.1 R110.2 U4.21 | length 3366.6
  Top Layer w8: C52.2@1180.91,2365 1205.31,2365 1210,2369.69 1210,2393.11 1227.5,2410.61 1249.95,2433.06 1265.51,2448.62 U4.21@1265.51,2474.9
  Top Layer w10: C52.2@1180.91,2365 1182.91,2362.99 C56.1@1182.91,2300 1182.91,2255.86 1188.77,2250 1247.37,2250 1303.12,2194.25 1751.1,2194.25 1752.35,2193 2258.21,2193 2298,2153.21 2298,1546.13 2298,929.84 2290.16,922 1843.88,922 1768.88,847 1689.26,847 1673.44,831.18 R110.2@1673.44,796.5 ; U4.21@1265.51,2474.9 U4.21@1265.51,2491.18
A2_VC8: C52.1 C81.2 R93.2 U4.19 | length 2549.1
  Top Layer w8: C52.1@1117.91,2365 1118.9,2365 1133.6,2379.7 1133.6,2388.3 1176.3,2431 1197.76,2431 1224.24,2457.48 U4.19@1224.24,2479.28 ; U4.19@1224.24,2489.28 U4.19@1226.14,2491.18
  Top Layer w10: C52.1@1117.91,2365 1110.91,2357.99 C81.2@1110.91,2300 1110.91,2224.09 1118.75,2216.25 1251.12,2216.25 1289.12,2178.25 1744.47,2178.25 1745.72,2177 1756.4,2177 1781,2152.4 1781,887.6 1756.4,863 1604.32,863 1572.5,831.18 R93.2@1572.5,796.5
A2_VC9: C77.2 C81.1 R210.2 U4.17 | length 3156.3
  Top Layer w8: C77.2@904.41,2448.5 1043.41,2448.5 1062.51,2467.6 1080,2467.6 1184.87,2467.6 1186.77,2469.51 U4.17@1186.77,2491.18
  Top Layer w10: C77.2@904.41,2448.5 904.41,2328.47 1032.63,2200.25 1227.37,2200.25 1265.37,2162.25 1737.84,2162.25 1739.09,2161 1749.77,2161 1765,2145.77 1765,894.23 1749.77,879 1519.38,879 1471.56,831.18 R210.2@1471.56,796.5 ; C81.1@1047.91,2300 1048.9,2300 1062.6,2313.7 1062.6,2314.69 1080,2332.09 1080,2467.6
A2_VC10: C73.2 C77.1 R194.2 U4.15 | length 3119.8
  Top Layer w8: C73.2@969.41,2512.01 969.41,2512.99 984.11,2527.69 1006.96,2527.69 1065,2585.73 1108.09,2585.73 U4.15@1110,2587.64
  Top Layer w10: C73.2@969.41,2511.5 C77.1@904.41,2511.5 871.86,2511.5 866,2505.64 866,2344.25 1026,2184.25 1220.75,2184.25 1258.75,2146.25 1731.21,2146.25 1732.47,2145 1743.14,2145 1749,2139.14 1749,900.86 1743.14,895 1380,895 1370.62,885.62 R194.2@1370.62,796.5
A2_VC11: C69.2 C73.1 R177.2 U4.13 | length 2354.2
  Top Layer w8: C73.1@969.41,2575.98 984.11,2590.69 1003,2590.69 1039.32,2627.01 U4.13@1095,2627.01
  Top Layer w10: C73.1@969.41,2575.98 C73.1@969.41,2575 965.91,2578.5 C69.2@904.41,2578.5 870.71,2578.5 850,2557.8 850,2337.63 1019.37,2168.25 1188.89,2168.25 1205,2152.14 1205,815 1222.52,797.48 1269.69,797.48 R177.2@1269.69,796.5 ; U4.13@1095,2627.01 U4.13@1110,2627.01
A2_VC12: C65.2 C69.1 R3.2 R161.2 U4.11 | length 2427.7
  Top Layer w8: C65.2@969.41,2642.01 969.41,2642.99 984.11,2657.69 997.69,2657.69 1006.38,2666.38 U4.11@1110,2666.38
  Top Layer w10: R3.2@799.41,2647.01 804.41,2642.01 904.41,2642.01 C65.2@969.41,2642.01 ; R3.2@800,2642.01 800,2365 1012.75,2152.25 1169.52,2152.25 1186,2135.77 1186,814.73 1168.75,797.48 R161.2@1168.75,796.5
A2_VC13: C61.2 C65.1 R3.1 R7.2 R145.2 U4.9 | length 2914.9
  Top Layer w8: C65.1@969.41,2705 974.41,2710 975.41,2711 985,2711 1059,2711 1064.25,2705.75 U4.9@1110,2705.75
  Top Layer w10: C65.1@985,2710 974.41,2710 969.41,2710 904.41,2710 799.41,2710 R7.2@734.41,2710 670,2710 660,2700 660,2205 728.75,2136.25 1162.89,2136.25 1170,2129.14 1170,898.68 1170,850 1150,830 1101.32,830 1082.5,811.18 1081.51,811.18 1067.81,797.48 R145.2@1067.81,796.5
A2_VC14: C57.2 C61.1 R4.2 R7.1 R129.2 U4.7 | length 2782.2
  Top Layer w8: C57.2@969.41,2778.5 1021.2,2778.5 1054.59,2745.12 U4.7@1110,2745.12
  Top Layer w10: C61.1@904.41,2771.5 C61.1@911.42,2778.5 ; R129.2@966.88,796.5 966.88,832.48 953.17,846.18 952.19,846.18 933.37,865 640.86,865 635,870.86 635,2765 648.5,2778.5 734.41,2778.5 799.41,2778.5 C61.1@911.42,2778.5 ; C57.2@969.41,2778.5 C61.1@911.42,2778.5
A2_VC15: C53.2 C57.1 R4.1 R8.2 R111.2 U4.5 | length 2786.9
  Top Layer w8: 1006.24,2841.5 1017.69,2841.5 1072.8,2786.39 1108.09,2786.39 U4.5@1110,2784.49
  Top Layer w10: R111.2@865.94,796.5 865.94,831.18 848.12,849 634.23,849 616,867.23 616,2831 628.5,2843.5 R8.2@734.41,2843.5 799.41,2843.5 902.91,2843.5 C53.2@904.41,2842.01 904.92,2841.5 C57.1@969.41,2841.5 1006.24,2841.5
A2_VC16: C53.1 R8.1 R94.2 R408.2 U4.3 | length 2802.9
  Top Layer w8: 1030,2885 1051.51,2863.49 1051.51,2847.28 1073.02,2825.76 1108.09,2825.76 U4.3@1110,2823.86
  Top Layer w10: R94.2@765,796.5 751.3,810.2 751.3,825.2 745,831.5 623.5,831.5 600,855 600,2900 606.5,2906.5 R8.1@734.41,2906.5 796.5,2906.5 800,2910 899.41,2910 C53.1@904.41,2905 904.41,2904.02 923.43,2885 1030,2885
A2N_NTC0_C: J2.1 RT1.1 | length 222.4
  Top Layer w10: J2.1@6926.02,2508.96 6971.92,2508.96 6984.9,2521.93 6984.9,2526.31 7009.45,2550.86 7122.67,2550.86 RT1.1@7126.81,2555
A2N_NTC1_C: J2.2 RT2.2 | length 118.3
  Top Layer w10: J2.2@7026.81,2508.96 7100.68,2508.96 7126.81,2482.83 RT2.2@7126.81,2475.33
A2N_NTC2_C: J2.3 RT3.1 | length 245.4
  Top Layer w10: J2.3@6926.02,2408.96 6930.4,2413.34 6971.92,2413.34 7009.45,2450.86 7079.11,2450.86 7126.81,2403.17 RT3.1@7126.81,2395.67
A2N_NTC3_C: J2.4 RT4.2 | length 142.9
  Top Layer w10: J2.4@7026.81,2408.96 7107.26,2328.5 7121.81,2328.5 7126.81,2323.5 RT4.2@7126.81,2316
A2N_NTC4_C: J2.7 RT5.1 | length 228.6
  Top Layer w10: J2.7@6926.02,2208.96 6930.4,2213.34 6971.92,2213.34 7009.45,2250.86 7119.78,2250.86 7126.81,2243.83 RT5.1@7126.81,2236.33
A2N_NTC5_C: J2.8 RT6.2 | length 126.1
  Top Layer w10: J2.8@7026.81,2208.96 7082.02,2208.96 7126.81,2164.17 RT6.2@7126.81,2156.67
A2N_NTC6_C: J2.9 RT7.1 | length 253.1
  Top Layer w10: J2.9@6926.02,2108.96 6930.4,2113.34 6971.92,2113.34 7009.45,2150.86 7060.44,2150.86 7126.81,2084.5 RT7.1@7126.81,2077
A2N_NTC7_C: J2.10 RT8.2 | length 153
  Top Layer w10: J2.10@7026.81,2108.96 7026.81,2104.83 7126.81,2004.83 RT8.2@7126.81,1997.33
A2N_NTC8_C: J2.13 RT9.1 | length 236.3
  Top Layer w10: J2.13@6926.02,1908.96 6930.4,1913.34 6971.92,1913.34 7009.45,1950.86 7101.11,1950.86 7126.81,1925.17 RT9.1@7126.81,1917.67
A2N_NTC9_C: J2.14 RT10.2 | length 133.8
  Top Layer w10: J2.14@7026.81,1908.96 7036.17,1899.6 7072.71,1899.6 7126.81,1845.5 RT10.2@7126.81,1838
A2N_NTC10_C: J2.15 RT11.1 | length 262.3
  Top Layer w10: J2.15@6926.02,1808.96 6930.4,1813.34 6971.92,1813.34 7009.45,1850.86 7044.16,1850.86 7121.81,1773.22 7121.81,1763.33 RT11.1@7126.81,1758.33
A2N_NTC11_C: J2.16 RT12.2 | length 171.7
  Top Layer w10: J2.16@7026.81,1808.96 7124.59,1711.17 7124.59,1680.88 RT12.2@7126.81,1678.67
A2N_NTC12_C: J2.19 RT13.1 | length 244
  Top Layer w10: J2.19@6926.02,1608.96 6930.4,1613.34 6971.92,1613.34 7009.45,1650.86 7082.44,1650.86 7126.81,1606.5 RT13.1@7126.81,1599
A2N_NTC13_C: J2.20 RT14.2 | length 141.5
  Top Layer w10: J2.20@7026.81,1608.96 7103.93,1531.83 7121.81,1531.83 7126.81,1526.83 RT14.2@7126.81,1519.33
A2N_NTC14_C: J2.21 RT15.1 | length 280.9
  Top Layer w10: J2.21@6926.02,1508.96 6930.4,1513.34 6971.92,1513.34 7009.45,1550.86 7044.16,1550.86 7126.81,1468.22 RT15.1@7126.81,1439.67
A2N_NTC15_C: J2.22 RT16.2 | length 190.4
  Top Layer w10: J2.22@7026.81,1508.96 7026.81,1496.61 7126.81,1396.61 RT16.2@7126.81,1360
ISO_A1_COMML_N: D8.2 J30.1 J32.2 T1.6 | length 352.7
  Top Layer w10: J30.1@6307.36,3495 6312.36,3490 J32.2@6312.36,3385 ; J32.2@6320,3380 6321.22,3378.78 6321.22,3335.47 6381.69,3275 D8.2@6381.69,3260 6381.69,3228.31 6415,3195 T1.6@6415,3178.76
ISO_A1_COMML_P: D8.1 J30.2 J32.1 T1.4 | length 424.5
  Top Layer w10: J32.1@6407.36,3390 J30.2@6407.36,3495 ; J32.1@6420,3380 6468.31,3331.69 D8.1@6468.31,3260 6575,3260 6615,3220 T1.4@6615,3203.76
ISO_A2_COMMH_N: D9.1 J31.4 J33.1 T2.1 | length 829.5
  Top Layer w10: T2.1@3127.52,2750 3137.48,2759.96 3169.96,2759.96 3265,2855 3265,3275 J33.1@3270,3280 3270,3383.31 D9.1@3253.31,3400 ; D9.1@3254.15,3400.85 3254.15,3494.15 J31.4@3255,3495
ISO_A2_COMMH_P: D9.2 J31.3 J33.2 T2.3 | length 562.1
  Top Layer w10: T2.3@3127.52,2950 3135,2957.48 3135,2965 3165,2995 J33.2@3165,3280 ; J31.3@3155,3495 3160.85,3489.15 3160.85,3405.85 D9.2@3166.69,3400 ; J33.2@3170,3280 D9.2@3170,3396.69
NetC3_2: C3.2 Q1.2 R24.1
  other v2: 2322.64,3107.02 2387.64,3107.02 2452.64,3107.02 2530,3115 2387.64,3177.02 2452.64,3177.02 2517.64,3177.02 2387.64,3237.02 2452.64,3237.02 2517.64,3237.02 2322.64,3302.02 2387.64,3302.02 2452.64,3302.02 2517.64,3302.02 2577.57,3302.02 2642.57,3302.02 2322.64,3372.02 2387.64,3372.02 2452.64,3372.02 2517.64,3372.02 2577.57,3372.02 2642.57,3372.02 2322.64,3442.02 2387.64,3442.02 2452.64,3442.02 2517.64,3442.02 2577.57,3442.02 2642.57,3442.02 2452.64,3512.02 2517.64,3512.02 2577.57,3512.02 2642.57,3512.02 2452.64,3582.02 2517.64,3582.02 2577.57,3582.02 2642.57,3582.02 2452.64,3652.02 2517.64,3652.02 2577.57,3652.02 2642.57,3652.02 2452.64,3712.02 2517.64,3712.02 2577.57,3712.02 2642.57,3712.02 2452.64,3767.02 2517.64,3767.02 2577.57,3767.02 2642.57,3767.02
NetC10_2: C10.2 R68.2 | length 64.9
  Top Layer w10: R68.2@1695.91,2785 C10.2@1760.79,2785
NetC30_1: C30.1 R46.2 R47.2 | length 144.1
  Top Layer w10: R46.2@426.5,3080 C30.1@495,3080 563.5,3080 R47.2@568.5,3075
NetC30_2: C30.2 R50.2 R51.2 | length 138.4
  Top Layer w8: R50.2@430,3140 485,3140 C30.2@488.5,3136.5 ; C30.2@492.01,3140 C30.2@488.5,3136.5 ; R51.2@562.01,3136.5 C30.2@488.5,3136.5
NetC46_1: C46.1 T1.2 | length 131.5
  Top Layer w10: v2(6509.35,2659.84) 6511.65,2662.14 6511.65,2707.89 T1.2@6515,2711.24
  Bottom Layer w10: v2(6509.35,2659.84) 6509.35,2656.59 6520,2645.94 C46.1@6520,2586.5
NetC47_1: C47.1 T2.5 | length 126.8
  Top Layer w10: v2(2600,2870) 2603.25,2870 2613.8,2859.45 2650.55,2859.45 T2.5@2660,2850
  Bottom Layer w10: C47.1@2580.91,2820 2581.89,2820 2595.59,2833.7 2595.59,2862.34 2600,2866.75 v2(2600,2870)
NetC154_2: C154.2 Q39.2 R151.1 | length 204.7
  Top Layer w10: R151.1@5662.91,3600 5682.47,3580.44 v2(5820,3580.44) ; C154.2@5715.44,3235.44 v2(5755,3235.44)
  other v2: 5690,3105.44 5755,3105.44 5820,3105.44 5885,3105.44 5755,3175.44 5820,3175.44 5885,3175.44 5820,3235.44 5885,3235.44 5690,3300.44 5755,3300.44 5820,3300.44 5885,3300.44 5944.93,3300.44 6009.93,3300.44 5690,3370.44 5755,3370.44 5820,3370.44 5885,3370.44 5944.93,3370.44 6009.93,3370.44 5690,3440.44 5755,3440.44 5820,3440.44 5885,3440.44 5944.93,3440.44 6009.93,3440.44 5820,3510.44 5885,3510.44 5944.93,3510.44 6009.93,3510.44 5885,3580.44 5944.93,3580.44 6009.93,3580.44 5820,3650.44 5885,3650.44 5944.93,3650.44 6009.93,3650.44 5820,3710.44 5885,3710.44 5944.93,3710.44 6009.93,3710.44 5820,3765.44 5885,3765.44 5944.93,3765.44 6009.93,3765.44
NetC159_2: C159.2 R155.2 | length 64.9
  Top Layer w10: R155.2@5063.27,2785 C159.2@5128.15,2785
NetC179_1: C179.1 R173.2 R174.2 | length 146.2
  Top Layer w8: R173.2@3793.86,3055 3850.87,3055 3852.36,3053.5 3855.87,3050 3930.87,3050 R174.2@3935.87,3055
NetC179_2: C179.2 R182.2 R183.2 | length 138.4
  Top Layer w8: R182.2@3793.86,3120 3848.86,3120 3852.36,3116.5 3855.87,3120 R183.2@3929.37,3120
NetD1_2: D1.2 R30.1 | length 60
  Top Layer w10: R30.1@1776.5,2600 1776.5,2545 D1.2@1780,2541.5
NetD4_1: D4.1 Q2.2 Q2.4 | length 237.9
  Bottom Layer w10: D4.1@1971.34,1115 1976.96,1120.62 Q2.4@2104.57,1120.62
  Bottom Layer w40: Q2.4@2104.57,1120.62 Q2.2@2206.93,1120.62
NetD4_2: D4.2 R97.2 | length 156.6
  Bottom Layer w10: R97.2@1845,976.5 1845,1071.34 D4.2@1888.66,1115
NetD5_1: D5.1 Q3.2 Q3.4 | length 230.8
  Bottom Layer w10: D5.1@299.29,1783.75 299.68,1784.15 Q3.4@427.52,1784.15
  Bottom Layer w40: Q3.4@427.52,1784.15 Q3.2@529.88,1784.15
NetD5_2: D5.2 R98.2 | length 215
  Bottom Layer w10: R98.2@212.95,1570.25 212.95,1780.09 D5.2@216.61,1783.75
NetD10_1: D10.1 Q5.2 Q5.4 | length 251.1
  Bottom Layer w10: D10.1@1961.5,1531.84 1972.24,1542.59 2005.93,1542.59 2008.96,1545.62 Q5.4@2104.57,1545.62
  Bottom Layer w40: Q5.4@2104.57,1545.62 Q5.2@2206.93,1545.62
NetD10_2: D10.2 R114.2 | length 182.8
  Bottom Layer w10: R114.2@1845,1371.5 1841.82,1374.68 1841.82,1488.03 1863.79,1510 1866.82,1510 D10.2@1888.66,1531.84
NetD11_1: D11.1 Q4.2 Q4.4 | length 232.7
  Bottom Layer w10: D11.1@299.29,2443.75 304.29,2448.75 Q4.4@427.52,2448.75
  Bottom Layer w40: Q4.4@427.52,2448.75 Q4.2@529.88,2448.75
NetD11_2: D11.2 R115.2 | length 158.6
  Bottom Layer w10: R115.2@207.95,2288.75 216.61,2297.42 D11.2@216.61,2443.75
NetD16_1: D16.1 Q6.2 Q6.4 | length 251.1
  Bottom Layer w10: D16.1@1961.49,1921.22 1972.24,1931.97 2101.54,1931.97 Q6.4@2104.57,1935
  Bottom Layer w40: Q6.4@2104.57,1935 Q6.2@2206.93,1935
NetD16_2: D16.2 R132.2 | length 161.3
  Bottom Layer w10: R132.2@1845,1777.99 1845,1877.56 D16.2@1888.66,1921.22
NetD17_1: D17.1 Q7.2 Q7.4 | length 258.3
  Bottom Layer w10: D17.1@856.34,1135 861.73,1140.39 Q7.4@1010,1140.39
  Bottom Layer w40: Q7.4@1010,1140.39 Q7.2@1112.36,1140.39
NetD17_2: D17.2 R133.2 | length 240.4
  Bottom Layer w10: R133.2@685,976.5 685,1120 705,1140 D17.2@773.66,1140
NetD22_1: D22.1 Q8.2 Q8.4 | length 243.4
  Bottom Layer w10: D22.1@2510,1120 2525.62,1135.62 Q8.4@2644.57,1135.62
  Bottom Layer w40: Q8.4@2644.57,1135.62 Q8.2@2746.93,1135.62
NetD22_2: D22.2 R148.2 | length 161
  Bottom Layer w10: R148.2@2385,976.5 2385,1077.68 D22.2@2427.32,1120
NetD23_1: D23.1 Q9.2 Q9.4 | length 254.6
  Bottom Layer w10: D23.1@860,1530 865.39,1535.39 Q9.4@1010,1535.39
  Bottom Layer w40: Q9.4@1010,1535.39 Q9.2@1112.36,1535.39
NetD23_2: D23.2 R149.2 | length 248.5
  Bottom Layer w10: R149.2@700,1357.99 700,1525 710,1535 D23.2@777.32,1535
NetD28_1: D28.1 Q10.2 Q10.4 | length 240.6
  Bottom Layer w10: D28.1@2501.34,1545 Q10.4@2639.57,1545
  Bottom Layer w40: Q10.4@2639.57,1545 Q10.2@2741.93,1545
NetD28_2: D28.2 R164.2 | length 177.4
  Bottom Layer w10: R164.2@2385,1381.5 2385,1476.34 2418.66,1510 D28.2@2418.66,1545
NetD29_1: D29.1 Q11.2 Q11.4 | length 252.4
  Bottom Layer w10: D29.1@860,1925 Q11.4@1010,1925
  Bottom Layer w40: Q11.4@1010,1925 Q11.2@1112.36,1925
NetD29_2: D29.2 R165.2 | length 238.5
  Bottom Layer w10: R165.2@700,1757.99 700,1915 710,1925 D29.2@777.32,1925
NetD34_1: D34.1 Q12.2 Q12.4 | length 242.9
  Bottom Layer w10: D34.1@2496.34,1945 2501.96,1950.62 Q12.4@2634.57,1950.62
  Bottom Layer w40: Q12.4@2634.57,1950.62 Q12.2@2736.93,1950.62
NetD34_2: D34.2 R180.2 | length 172.4
  Bottom Layer w10: R180.2@2390,1786.5 2385,1791.5 2385,1916.34 D34.2@2413.66,1945
NetD35_1: D35.1 Q13.2 Q13.4 | length 247.1
  Bottom Layer w10: D35.1@1411.22,1130 1421.96,1140.75 1544.92,1140.75 Q13.4@1549.57,1145.39
  Bottom Layer w40: Q13.4@1549.57,1145.39 Q13.2@1651.93,1145.39
NetD35_2: D35.2 R181.2 | length 205.2
  Bottom Layer w10: R181.2@1275,976.5 1275,1110 1295,1130 D35.2@1338.38,1130
NetD41_1: D41.1 Q14.2 Q14.4 | length 241.9
  Bottom Layer w10: D41.1@3061.34,1220 3061.34,1229.84 3062.24,1230.75 3072.09,1230.75 3081.34,1240 3172.64,1240 Q14.4@3182.64,1230
  Bottom Layer w40: Q14.4@3182.64,1230 Q14.2@3285,1230
NetD41_2: D41.2 R197.2 | length 269.5
  Bottom Layer w10: R197.2@2940,966.5 2940.07,966.56 2940.07,1181.4 D41.2@2978.66,1220
NetD42_1: D42.1 Q15.2 Q15.4 | length 239.7
  Bottom Layer w10: D42.1@1411.21,1535 1421.9,1545.69 Q15.4@1544.13,1545.69
  Bottom Layer w40: Q15.4@1544.13,1545.69 Q15.2@1646.5,1545.69
NetD42_2: D42.2 R198.2 | length 223.6
  Bottom Layer w10: R198.2@1275,1361.5 1273.38,1363.12 1273.38,1508.38 1300,1535 D42.2@1338.38,1535
NetD45_2: D45.2 R157.1 | length 60
  Top Layer w10: R157.1@5143.86,2600 5143.86,2545 D45.2@5147.36,2541.5
NetD47_1: D47.1 Q16.2 Q16.4 | length 234.9
  Bottom Layer w10: D47.1@3056.34,1850 3071.34,1865 Q16.4@3182.64,1865
  Bottom Layer w40: Q16.4@3182.64,1865 Q16.2@3285,1865
NetD47_2: D47.2 R213.2 | length 281.9
  Bottom Layer w10: R213.2@2935,1591.5 2926.05,1600.44 2926.05,1802.39 D47.2@2973.66,1850
NetD48_1: D48.1 Q17.2 Q17.4 | length 230.2
  Bottom Layer w10: D48.1@1421.06,1930 1431.46,1940.39 Q17.4@1544.57,1940.39
  Bottom Layer w40: Q17.4@1544.57,1940.39 Q17.2@1646.93,1940.39
NetD48_2: D48.2 R214.2 | length 206
  Bottom Layer w10: R214.2@1280,1776.5 1280,1920 1290,1930 D48.2@1338.39,1930
NetD57_1: D57.1 Q40.2 Q40.4 | length 237.9
  Bottom Layer w10: D57.1@5338.7,1115 5344.32,1120.62 Q40.4@5471.93,1120.62
  Bottom Layer w40: Q40.4@5471.93,1120.62 Q40.2@5574.29,1120.62
NetD57_2: D57.2 R425.2 | length 156.6
  Bottom Layer w10: R425.2@5212.36,976.5 5212.36,1071.34 D57.2@5256.02,1115
NetD58_1: D58.1 Q41.2 Q41.4 | length 225.2
  Bottom Layer w10: D58.1@3672.04,1784.15 Q41.4@3794.88,1784.15
  Bottom Layer w40: Q41.4@3794.88,1784.15 Q41.2@3897.24,1784.15
NetD58_2: D58.2 R426.2 | length 220.6
  Bottom Layer w10: R426.2@3580.31,1570.25 3580.31,1780.09 D58.2@3583.97,1783.75 ; D58.2@3588.35,1786.25 3587.96,1785.85 D58.2@3592.96,1785.85
NetD59_1: D59.1 Q43.2 Q43.4 | length 251.1
  Bottom Layer w10: D59.1@5328.86,1531.84 5339.61,1542.59 5468.9,1542.59 Q43.4@5471.93,1545.62
  Bottom Layer w40: Q43.4@5471.93,1545.62 Q43.2@5574.29,1545.62
NetD59_2: D59.2 R435.2 | length 182.8
  Bottom Layer w10: R435.2@5212.36,1371.5 5209.18,1374.68 5209.18,1488.03 5231.15,1510 5234.18,1510 D59.2@5256.02,1531.84
NetD60_1: D60.1 Q42.2 Q42.4 | length 232.7
  Bottom Layer w10: D60.1@3666.65,2443.75 3671.65,2448.75 Q42.4@3794.88,2448.75
  Bottom Layer w40: Q42.4@3794.88,2448.75 Q42.2@3897.24,2448.75
NetD60_2: D60.2 R436.2 | length 158.6
  Bottom Layer w10: R436.2@3575.31,2288.75 3583.97,2297.42 D60.2@3583.97,2443.75
NetD61_1: D61.1 Q44.2 Q44.4 | length 251.1
  Bottom Layer w10: D61.1@5328.86,1921.22 5339.6,1931.97 5468.9,1931.97 Q44.4@5471.93,1935
  Bottom Layer w40: Q44.4@5471.93,1935 Q44.2@5574.29,1935
NetD61_2: D61.2 R445.2 | length 161.3
  Bottom Layer w10: R445.2@5212.36,1777.99 5212.36,1877.56 D61.2@5256.02,1921.22
NetD62_1: D62.1 Q45.2 Q45.4 | length 258.3
  Bottom Layer w10: D62.1@4223.7,1135 4229.09,1140.39 Q45.4@4377.36,1140.39
  Bottom Layer w40: Q45.4@4377.36,1140.39 Q45.2@4479.72,1140.39
NetD62_2: D62.2 R446.2 | length 240.4
  Bottom Layer w10: R446.2@4052.36,976.5 4052.36,1120 4072.36,1140 D62.2@4141.02,1140
NetD63_1: D63.1 Q46.2 Q46.4 | length 253.2
  Bottom Layer w10: D63.1@5867.52,1120 5878.27,1130.75 5911.7,1130.75 5916.57,1135.62 Q46.4@6011.93,1135.62
  Bottom Layer w40: Q46.4@6011.93,1135.62 Q46.2@6114.29,1135.62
